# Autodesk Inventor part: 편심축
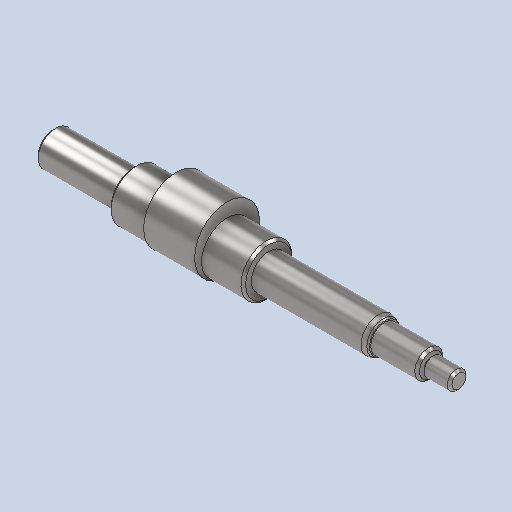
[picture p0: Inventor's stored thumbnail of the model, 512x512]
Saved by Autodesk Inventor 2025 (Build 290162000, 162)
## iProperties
Created: 2025-08
Part Number: 편심축
Material: 강철, 연강
Document SubType Name: Modeling
Designer: infra017
Density: 7.86 g/cm^3
Appearance: 기본값
Author: jhkim
Sending System: Autodesk Inventor 2026
Preprocessor: ST-DEVELOPER v20.1
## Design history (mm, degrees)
feature "솔리드1"
node "솔리드2"
